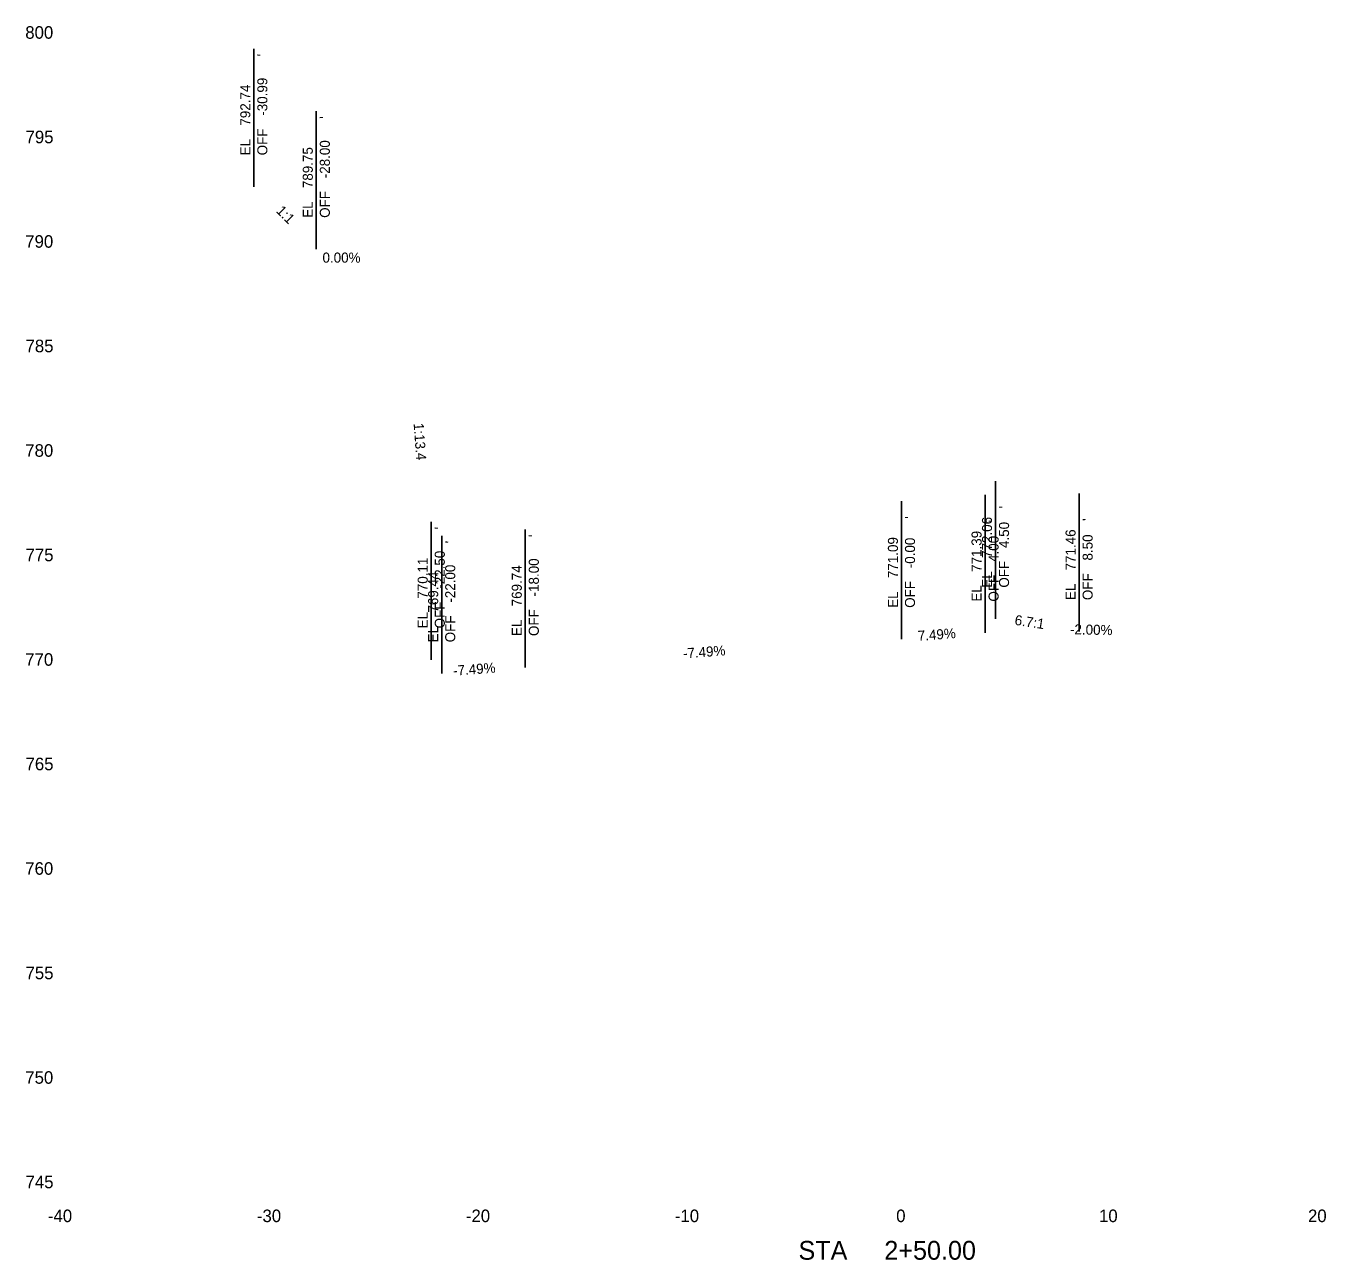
# Model space of a CAD drawing. Extents: x -42 to 102, y 742 to 803.
# Drawn here: x -41.9 to 20.3, y 741.7 to 800.7 of the extents above; entities that cross this region are included whole.
import ezdxf

# ---------------------------------------------------------------- set-up
doc = ezdxf.new("R2010")
doc.units = 0
for name, color, linetype in [('XS-Feature Text', 7, 'Continuous'), ('XS-Segment Text', 7, 'Continuous'), ('XS-Text', 7, 'Continuous')]:
    doc.layers.add(name, color=color, linetype=linetype)

msp = doc.modelspace()

# ---------------------------------------------------------------- linework, layer by layer
at = {"layer": 'XS-Feature Text'}
for p, q in [((-30.99, 793.04), (-30.99, 799.64)), ((-28, 790.05), (-28, 796.65)), ((4.5, 772.357), (4.5, 778.957)), ((4, 771.69), (4, 778.29)), ((8.5, 771.76), (8.5, 778.36)), ((8.5, 771.759), (8.5, 778.359)), ((0, 771.391), (0, 777.991)), ((-22.5, 770.409), (-22.5, 777.009)), ((-22, 769.742), (-22, 776.342)), ((-18, 770.042), (-18, 776.642))]:
    msp.add_line(p, q, dxfattribs=at)

# ---------------------------------------------------------------- texts
for s, p in [("'", (-30.342, 799.277)), ('-30.99', (-30.342, 796.435)), ('792.74', (-31.158, 795.961)), ("'", (-27.352, 796.286)), ('OFF ', (-30.342, 794.54)), ('EL ', (-31.158, 794.54)), ('-28.00', (-27.352, 793.444)), ('789.75', (-28.168, 792.971)), ('OFF ', (-27.352, 791.55)), ('EL ', (-28.168, 791.55)), ("'", (5.148, 777.646)), ("'", (0.648, 777.153)), ('772.06', (4.332, 775.278)), ("'", (4.648, 776.979)), ('4.50', (5.148, 775.752)), ("'", (9.148, 777.049)), ("'", (9.148, 777.048)), ("'", (-21.852, 776.645)), ("'", (-17.352, 776.278)), ('771.39', (3.832, 774.611)), ('771.46', (8.332, 774.681)), ('771.46', (8.332, 774.68)), ('8.50', (9.148, 775.155)), ('8.50', (9.148, 775.153)), ("'", (-21.352, 775.978)), ('771.09', (-0.168, 774.312)), ('-0.00', (0.648, 774.785)), ('4.00', (4.648, 775.085)), ('770.11', (-22.668, 773.33)), ('-22.50', (-21.852, 773.804)), ('-18.00', (-17.352, 773.436)), ('OFF ', (5.148, 773.857)), ('769.44', (-22.168, 772.663)), ('-22.00', (-21.352, 773.137)), ('769.74', (-18.168, 772.963)), ('EL ', (4.332, 773.857)), ('OFF ', (9.148, 773.26)), ('OFF ', (9.148, 773.259)), ('OFF ', (0.648, 772.891)), ('EL ', (3.832, 773.19)), ('OFF ', (4.648, 773.19)), ('EL ', (8.332, 773.26)), ('EL ', (8.332, 773.259)), ('EL ', (-0.168, 772.891)), ('EL ', (-22.668, 771.909)), ('OFF ', (-21.852, 771.909)), ('OFF ', (-17.352, 771.542)), ('EL ', (-22.168, 771.242)), ('OFF ', (-21.352, 771.242)), ('EL ', (-18.168, 771.542))]:
    msp.add_text(s, height=0.48, rotation=90, dxfattribs=at).set_placement(p)
at = {"layer": 'XS-Segment Text'}
for s, rotation, p in [('1:1', 315, (-29.952, 791.852)), ('0.00%', 360, (-27.704, 789.408)), ('1:13.4', 274.25926, (-23.345, 781.716)), ('6.7:1', 351.4904, (5.394, 772.081)), ('-2.00%', 358.85424, (8.06, 771.625)), ('7.49%', 4.28498, (0.799, 771.308)), ('-7.49%', 4.28498, (-10.437, 770.467)), ('-7.49%', 4.28498, (-21.437, 769.642))]:
    msp.add_text(s, height=0.48, rotation=rotation, dxfattribs=at).set_placement(p)
at = {"layer": 'XS-Text'}
for s, height, p in [('800', 0.6, (-41.926, 800.12)), ('795', 0.6, (-41.913, 795.12)), ('790', 0.6, (-41.926, 790.12)), ('785', 0.6, (-41.913, 785.12)), ('780', 0.6, (-41.926, 780.12)), ('775', 0.6, (-41.913, 775.12)), ('770', 0.6, (-41.926, 770.12)), ('765', 0.6, (-41.913, 765.12)), ('760', 0.6, (-41.926, 760.12)), ('755', 0.6, (-41.913, 755.12)), ('750', 0.6, (-41.926, 750.12)), ('745', 0.6, (-41.913, 745.12)), ('-40', 0.6, (-40.843, 743.5)), ('-30', 0.6, (-30.843, 743.5)), ('-20', 0.6, (-20.843, 743.5)), ('-10', 0.6, (-10.843, 743.5)), ('0', 0.6, (-0.251, 743.5)), ('10', 0.6, (9.453, 743.5)), ('20', 0.6, (19.453, 743.5)), (' STA ', 0.9, (-5.261, 741.7)), ('2+50.00', 0.9, (-0.82, 741.7))]:
    msp.add_text(s, height=height, dxfattribs=at).set_placement(p)

doc.saveas('drawing.dxf')
